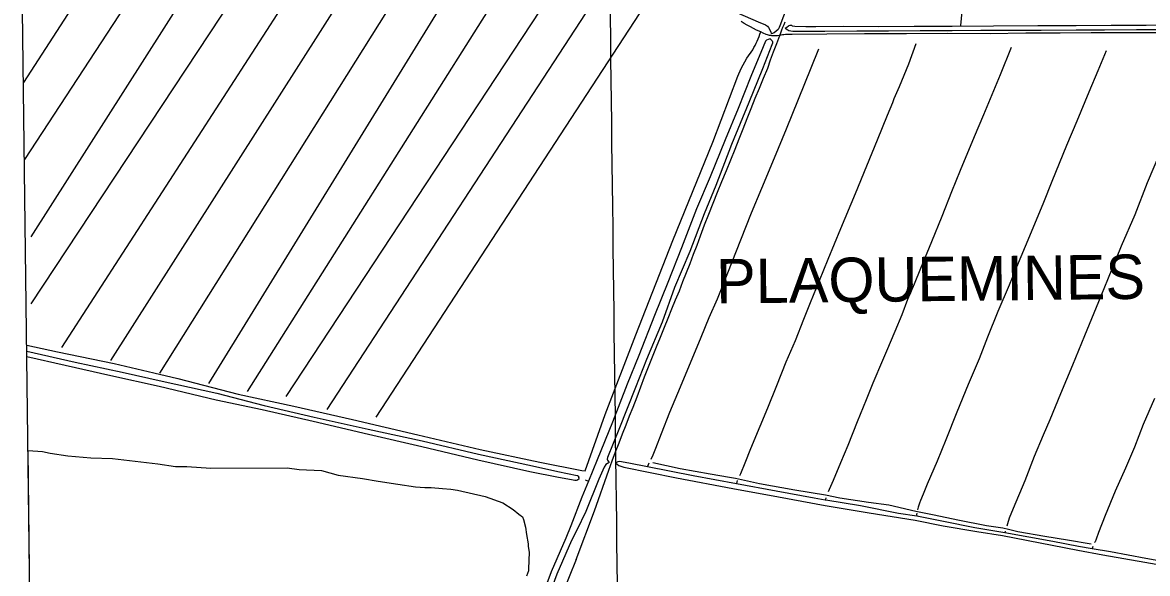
# Model space of a CAD drawing. Extents: x 3734862 to 3772949, y 391520 to 417239.
# Drawn here: x 3738996 to 3744064, y 399494 to 401975 of the extents above; entities that cross this region are included whole.
import ezdxf

# ---------------------------------------------------------------- set-up
doc = ezdxf.new("R2010")
doc.units = 0
for name, color, linetype in [('V-DTCH-CNTR', 7, 'Continuous'), ('V-GRID-FRAM', 7, 'Continuous'), ('V-GRID-MAJR', 7, 'Continuous'), ('V-SITE-VEGE', 7, 'Continuous'), ('V-TOPO-GNAM-IDEN', 7, 'Continuous'), ('V-TOPO-SHOR', 7, 'Continuous')]:
    doc.layers.add(name, color=color, linetype=linetype)

msp = doc.modelspace()

# ---------------------------------------------------------------- linework, layer by layer
at = {"layer": 'V-DTCH-CNTR'}
for points in [[(3741637.2, 399960.4), (3741652.4, 400001.1), (3741667.7, 400041.8), (3741683.2, 400082.4), (3741698.9, 400122.9), (3741714.8, 400163.4), (3741730.9, 400203.7), (3741747.2, 400244), (3741764.1, 400289.2), (3741781.2, 400334.4), (3741798.4, 400379.5), (3741815.8, 400424.5), (3741833.4, 400469.5), (3741851.2, 400514.4), (3741869.2, 400559.2), (3741887.3, 400603.9), (3741904.5, 400644.7), (3741921.4, 400685.5), (3741938.1, 400726.4), (3741954.7, 400767.4), (3741971, 400808.5), (3741987.2, 400849.6), (3742003.1, 400890.8), (3742018.9, 400932.1), (3742034.4, 400973.5), (3742049.8, 401015), (3742068.7, 401064), (3742087.8, 401113.1), (3742107.2, 401162), (3742126.7, 401210.8), (3742146.4, 401259.6), (3742166.4, 401308.3), (3742186.5, 401356.9), (3742206.8, 401405.5), (3742224.4, 401451.4), (3742242.1, 401497.2), (3742260.1, 401542.9), (3742278.2, 401588.6), (3742296.6, 401634.2), (3742315.1, 401679.7), (3742333.9, 401725.1), (3742352.9, 401770.4), (3742366, 401807.3), (3742379.5, 401844), (3742393.2, 401880.7), (3742407.1, 401917.3), (3742411.7, 401929.6), (3742416.5, 401941.8), (3742421.5, 401953.9), (3742426.6, 401966), (3742432, 401977.9)], [(3742346.2, 401921.2), (3742331.7, 401927.8), (3742321.1, 401932.8), (3742303, 401941.6), (3742288.9, 401948.8), (3742274.8, 401956.2), (3742260.8, 401963.8), (3742247, 401971.6), (3742233.2, 401979.5)], [(3742285.9, 401852.7), (3742291, 401862.4), (3742296, 401872.2), (3742300.7, 401882), (3742305.2, 401892), (3742309.5, 401902.1), (3742313.6, 401912.2), (3742317.5, 401922.5), (3742321.1, 401932.8)], [(3742411.5, 401918.1), (3742407.1, 401917.3), (3742404.3, 401916.7), (3742397.1, 401915.1), (3742391.9, 401914.8), (3742386.8, 401914.6), (3742381.6, 401914.7), (3742376.4, 401915), (3742371.3, 401915.5), (3742366.2, 401916.2), (3742361.1, 401917.1), (3742356.1, 401918.3), (3742351.1, 401919.6), (3742346.2, 401921.2)], [(3744183.5, 401928.6), (3743995.1, 401929.4), (3743810.5, 401929.2), (3743670, 401928), (3743515.6, 401926.8), (3743355.4, 401924.8), (3743161.8, 401925.4), (3742978.6, 401925.1), (3742789, 401923.7), (3742619.8, 401923.5), (3742462.7, 401921.3), (3742455.3, 401921.6), (3742448, 401921.6), (3742440.6, 401921.3), (3742433.3, 401920.9), (3742426, 401920.2), (3742418.7, 401919.2), (3742411.5, 401918.1)], [(3739014.9, 400522.6), (3739153.8, 400492.2), (3739408.1, 400440.3), (3739587.6, 400397.3), (3739695.6, 400372.2), (3739966.8, 400302.6), (3740217.9, 400248.3), (3740482.5, 400187.5), (3740776.1, 400119.5), (3741058, 400053.2), (3741325.9, 399996.2), (3741515.7, 399958.9), (3741530.6, 399956.2), (3741620.4, 400209.7), (3741758.2, 400568.6), (3741926, 400993.5), (3742105.4, 401436.2), (3742217.8, 401734.2), (3742232.6, 401768.4), (3742259.4, 401815.2), (3742285.9, 401852.7)], [(3741489.2, 399558.2), (3741572.7, 399776.7), (3741637.2, 399960.4)], [(3743810.2, 399627.1), (3743703.4, 399645), (3743601.2, 399661.6), (3743478.9, 399682.2), (3743438, 399692.6), (3743412.6, 399698.6), (3743338.6, 399708.9), (3743209.8, 399734.4), (3743103, 399756.7), (3743019.6, 399773.9), (3742898.9, 399802.2), (3742806.5, 399814), (3742677.7, 399834.2), (3742613.4, 399846.5), (3742474.8, 399870.3), (3742315.7, 399897.7), (3742208.1, 399922.9), (3742180.3, 399926.9), (3742092.8, 399941.5), (3741958.2, 399966.2), (3741834.7, 399992.6)], [(3741489.2, 399558.2), (3741364.2, 399245.8), (3741261.7, 398998.2), (3741153.5, 398730.5), (3741045.3, 398490.1)]]:
    msp.add_lwpolyline(points, dxfattribs=at)
at = {"layer": 'V-GRID-FRAM'}
msp.add_lwpolyline([(3738832.3, 415033.8), (3770599.2, 415447.4), (3770843.8, 397266.6), (3739061.1, 396852.8), (3738832.3, 415033.8)], dxfattribs=at)
at = {"layer": 'V-GRID-MAJR'}
msp.add_spline([(3741709.6, 396887.3), (3741633, 402946.6), (3741556.3, 409006.9), (3741479.6, 415067.2), (3741479.6, 415068.3)], degree=3, dxfattribs=at)
at = {"layer": 'V-SITE-VEGE'}
for p, q in [((3739031.5, 399202.2), (3739020.9, 400048.5)), ((3739020.9, 400048.5), (3739086.3, 400044.1)), ((3739086.3, 400044.1), (3739119.8, 400035.9)), ((3739119.8, 400035.9), (3739199.4, 400023.8)), ((3739199.4, 400023.8), (3739304.1, 400015.9)), ((3739304.1, 400015.9), (3739400.5, 400012.2)), ((3739400.5, 400012.2), (3739605.8, 399988.2)), ((3739605.8, 399988.2), (3739685.4, 399976)), ((3739685.4, 399976), (3739735.6, 399976.3)), ((3739735.6, 399976.3), (3739844.5, 399968.4)), ((3739844.5, 399968.4), (3740187.8, 399970.2)), ((3740187.8, 399970.2), (3740242.3, 399962.1)), ((3740242.3, 399962.1), (3740342.8, 399958.4)), ((3740342.8, 399958.4), (3740418.3, 399937.9)), ((3740418.3, 399937.9), (3740527.2, 399921.7)), ((3740527.2, 399921.7), (3740598.5, 399909.5)), ((3740598.5, 399909.5), (3740686.5, 399897.4)), ((3740686.5, 399897.4), (3740766.1, 399885.2)), ((3740766.1, 399885.2), (3740808, 399881.3)), ((3740808, 399881.3), (3740837.3, 399881.4)), ((3740837.3, 399881.4), (3740887.6, 399877.5)), ((3740887.6, 399877.5), (3740925.3, 399873.5)), ((3740925.3, 399873.5), (3740954.6, 399869.5)), ((3740954.6, 399869.5), (3741080.4, 399840.8)), ((3741080.4, 399840.8), (3741160.1, 399811.9)), ((3741160.1, 399811.9), (3741206.3, 399782.8)), ((3741206.3, 399782.8), (3741231.5, 399762)), ((3741231.5, 399762), (3741248.3, 399749.6)), ((3741248.3, 399749.6), (3741252.6, 399737)), ((3741252.6, 399737), (3741261.1, 399703.6)), ((3741261.1, 399703.6), (3741265.5, 399670.1)), ((3741265.5, 399670.1), (3741274, 399628.3)), ((3741274, 399628.3), (3741274.1, 399615.7)), ((3741274.1, 399615.7), (3741278.4, 399590.6)), ((3741278.4, 399590.6), (3741274.6, 399515.2)), ((3741274.7, 399506.8), (3741266.4, 399481.7)), ((3741274.6, 399515.2), (3741274.7, 399506.8))]:
    msp.add_line(p, q, dxfattribs=at)
at = {"layer": 'V-TOPO-SHOR'}
for p, q in [((3743222.3, 401962.5), (3743396.4, 403726.5)), ((3739787.1, 402925.7), (3739000, 401704.7)), ((3740007.6, 402890.9), (3739004.4, 401357.9)), ((3740193.3, 402832.9), (3739032.8, 401010.9)), ((3740390.6, 402763.3), (3739032.8, 400709.1)), ((3740529.9, 402612.4), (3739172.1, 400511.8)), ((3740738.8, 402566), (3739392.6, 400453.8)), ((3740924.4, 402484.7), (3739613.1, 400395.8)), ((3741098.5, 402403.5), (3739833.6, 400349.4)), ((3741284.2, 402333.9), (3740007.6, 400314.6)), ((3741481.5, 402264.2), (3740181.7, 400291.3)), ((3741632.4, 402171.4), (3740367.4, 400233.3)), ((3741829.7, 402101.8), (3740587.9, 400198.5)), ((3741817, 399991.5), (3741811.1, 399976.5)), ((3741530.6, 399915.5), (3741545.9, 399910.1)), ((3742215.9, 399912.6), (3742212.3, 399899.5)), ((3743817.4, 399615.5), (3743814.3, 399607.1))]:
    msp.add_line(p, q, dxfattribs=at)
for points in [[(3743107.9, 403761.9), (3743106.7, 403735.1), (3743100.7, 403710.7), (3743055.4, 403597.8), (3742962, 403363.6), (3742893.8, 403191.4), (3742807.6, 402977), (3742748, 402820.3), (3742695.2, 402681.5), (3742645.2, 402560.6), (3742579.9, 402391.6), (3742517.9, 402240.5), (3742452.6, 402080.1), (3742407, 401959.8), (3742404.6, 401952.9), (3742400.6, 401943.9), (3742381.9, 401928.7), (3742369.5, 401924.4)], [(3739446.6, 403230.2), (3739590.3, 403169.1), (3739774.9, 403091.3), (3740015.3, 402982.1), (3740220.1, 402894.6), (3740445.6, 402798.1), (3740659.6, 402701.9), (3740935.5, 402580.5), (3741156, 402482.4), (3741363.4, 402391.9), (3741564.9, 402301.5), (3741789.2, 402201.7), (3741935.8, 402141), (3742147.3, 402049.4), (3742309.6, 401978.1), (3742342.6, 401965.5), (3742352.1, 401958.6), (3742356.7, 401953.2), (3742365.8, 401936.8), (3742369.5, 401924.4)], [(3742431.4, 401950.4), (3742439.4, 401954.4), (3742446.3, 401960.2), (3742448.7, 401961.8), (3742453.2, 401962.7), (3742459.7, 401963.1), (3742463.3, 401961.1), (3742474.7, 401959.1), (3742525.2, 401957.7), (3742569.7, 401958), (3742692, 401958.6), (3742853.6, 401957.4), (3743011.9, 401958.6), (3743183.7, 401959.5), (3743369.8, 401960.9), (3743570.2, 401961.9), (3743742.4, 401962.4), (3743899.8, 401963.2), (3744057.3, 401964), (3744214.7, 401964.8)], [(3742431.4, 401950.4), (3742442.7, 401941.9), (3742448.4, 401939.4), (3742466.3, 401937.1), (3742610.7, 401936.6), (3742753.8, 401937.4), (3742897, 401938.1), (3743040.1, 401938.8), (3743183.3, 401939.6), (3743312.1, 401940.2), (3743455.3, 401941), (3743584.1, 401941.6), (3743741.6, 401942.4), (3743870.4, 401943.1), (3744013.5, 401943.8), (3744171, 401944.6)], [(3742363.5, 401901.1), (3742355, 401898.2), (3742347.7, 401895.3), (3742342.9, 401890.8), (3742332, 401866), (3742277.2, 401731.5), (3742219.6, 401588.1), (3742161.1, 401446.6), (3742093.4, 401280.1), (3742032.6, 401135.8), (3741964.5, 400960.5), (3741903.3, 400805.3), (3741843.3, 400655.7), (3741772, 400476.7), (3741720.4, 400347.6), (3741653.6, 400176), (3741584.3, 400006.6), (3741545.9, 399910.1), (3741515.9, 399838.7), (3741465.9, 399709.1), (3741443.5, 399653.9)], [(3742363.5, 401901.1), (3742372.5, 401892.6), (3742374.1, 401887.7), (3742374.5, 401882.8), (3742371.3, 401875.1), (3742329.2, 401767.3), (3742267.5, 401615.1), (3742190.1, 401426.7), (3742118.4, 401242.1), (3742066.8, 401113.3), (3742001.6, 400944.5), (3741933.1, 400781.5), (3741876.7, 400625.8), (3741807.1, 400457.8), (3741756.6, 400331.2), (3741682.2, 400143.3), (3741630.6, 400017.4), (3741629.8, 400009.7), (3741631.4, 400004), (3741633.9, 399999.6), (3741638.4, 399993.7)], [(3744327.8, 401884), (3744293.7, 401802.9), (3744219, 401627.6), (3744142.8, 401444.7), (3744062.8, 401253.7), (3744006.2, 401109.7), (3743945.2, 400968), (3743883.2, 400816.5), (3743843.1, 400718.4), (3743779.8, 400565.1), (3743725.5, 400432.9), (3743671.1, 400303.1), (3743623, 400185.8), (3743593.8, 400117.9), (3743553.7, 400021.8), (3743510.7, 399912.2), (3743458.1, 399786.7), (3743440.3, 399742.9), (3743432.3, 399718.7), (3743429.8, 399707.2)], [(3742581.7, 401854.7), (3742547.4, 401769.5), (3742489.7, 401628), (3742435.8, 401495.1), (3742381.6, 401364.9), (3742324.8, 401227.2), (3742278.2, 401116.2), (3742230.6, 400995.7), (3742171.1, 400846.9), (3742124.5, 400730.1), (3742087.1, 400645.5), (3742051, 400556.4), (3742004, 400442.1), (3741946.5, 400304.4), (3741910.6, 400218.7), (3741873.4, 400123.3), (3741847.1, 400057.5), (3741835.3, 400027), (3741826, 400008.2)], [(3743020.4, 401878.7), (3742986.4, 401787.2), (3742944.3, 401685.6), (3742920.2, 401631.2), (3742914.4, 401613.8), (3742891.4, 401556.6), (3742846.4, 401445.3), (3742797.4, 401328.9), (3742746.2, 401203.7), (3742681.3, 401047), (3742623.2, 400908.9), (3742584.9, 400812.3), (3742544.5, 400712.7), (3742513.8, 400638), (3742476.2, 400542.7), (3742434.9, 400446.6), (3742392.4, 400340.1), (3742351.8, 400239.5), (3742317.1, 400155.6), (3742274.7, 400055.9), (3742249.8, 399990.8), (3742230.2, 399943.6), (3742226.2, 399934.1)], [(3743450, 401862.4), (3743400.3, 401739.5), (3743325, 401560.2), (3743283.5, 401460.2), (3743219.1, 401309), (3743181, 401212.7), (3743136.7, 401101.9), (3743090.4, 400987.5), (3743040.4, 400867), (3743011.9, 400797.6), (3742982.7, 400728), (3742956.9, 400659.5), (3742924.8, 400584.7), (3742888.3, 400495.9), (3742870.2, 400453.1), (3742826.5, 400351.2), (3742796, 400276.3), (3742756.1, 400176.9), (3742713.1, 400070.8), (3742680.2, 399992.4), (3742647.4, 399913.7), (3742629.3, 399873.2), (3742624.7, 399862.4)], [(3743877.4, 401848.2), (3743839.5, 401757.1), (3743799.9, 401661.7), (3743745.5, 401531.7), (3743698.7, 401420.9), (3743632.7, 401259.1), (3743594.6, 401165.5), (3743524.5, 400994.6), (3743481.7, 400892.2), (3743440.9, 400792.9), (3743390.1, 400673.6), (3743343.5, 400558.3), (3743304.8, 400461.3), (3743256.2, 400346), (3743205.4, 400221), (3743155.5, 400096.2), (3743115.4, 400000.6), (3743071.2, 399897), (3743052.5, 399851.6), (3743041.2, 399823.8), (3743036.5, 399811.1), (3743033.4, 399801.4), (3743030.7, 399793), (3743027.4, 399780.8)], [(3739015.2, 400495.1), (3739233.2, 400445.9), (3739444.4, 400400.4), (3739624.8, 400360.1), (3739870.5, 400307.1), (3740083.7, 400250.7), (3740309.9, 400198.8), (3740552.8, 400144.6), (3740796.4, 400091.5), (3741049.8, 400031.3), (3741293.8, 399978.7), (3741407.7, 399953.8), (3741494.1, 399936.4), (3741496.5, 399936.4), (3741499.8, 399932.4), (3741501, 399927.1), (3741503, 399922.3)], [(3739015.5, 400471.2), (3739188.7, 400432.3), (3739393.1, 400385.6), (3739612, 400338.5), (3739867.8, 400276.7), (3740075.3, 400233.2), (3740305.6, 400180.9), (3740553.7, 400122.3), (3740795.3, 400066), (3741046.3, 400005.8), (3741281.4, 399953.9), (3741410.7, 399928.7), (3741468.2, 399917.2), (3741483.2, 399915.3), (3741490.9, 399914.9), (3741495.8, 399915.8), (3741503, 399922.3)], [(3744095.6, 400281.8), (3744044.5, 400166), (3744004.4, 400063.9), (3743964.1, 399968), (3743918.6, 399864.7), (3743873.6, 399755.5), (3743843.5, 399678.6), (3743832.6, 399648.3), (3743827.3, 399637.5), (3743825.5, 399634.2)], [(3741638.4, 399993.7), (3741634.1, 399991.4), (3741630.8, 399989), (3741624.1, 399984.6), (3741615.4, 399973.9), (3741592.1, 399918.6), (3741533.6, 399773.7), (3741493, 399690.3), (3741468.5, 399642.9)], [(3741667.7, 399992.7), (3741678.7, 399998.2), (3741684.7, 399999.8), (3741727.3, 399992.3), (3741811.1, 399976.5), (3742017.5, 399935.1), (3742212.3, 399899.5), (3742391.2, 399866.2), (3742561.4, 399835.1), (3742612.2, 399826.5), (3742614.9, 399826), (3742771.3, 399800.1), (3742942, 399766.2), (3743025.1, 399754.4), (3743144.2, 399729.9), (3743285.7, 399702.3), (3743420.9, 399678.5), (3743637.9, 399640.2)], [(3741667.7, 399992.7), (3741674.7, 399987), (3741682, 399981.2), (3741704.7, 399972.8), (3741941.4, 399924.6), (3742196, 399877.7), (3742401.4, 399840.3), (3742612.2, 399801.3), (3742810.4, 399767.1), (3743016.7, 399734.5), (3743143.1, 399709.3), (3743295.5, 399682.9), (3743409.8, 399666.1), (3743634.4, 399622.7)], [(3742615.3, 399835.5), (3742614, 399831.7), (3742612.2, 399826.5)], [(3743024.1, 399766.8), (3743023.4, 399760.5), (3743025.1, 399754.4)], [(3741443.5, 399653.9), (3741376.8, 399502.3), (3741302.9, 399301.1), (3741237.7, 399121.9), (3741165.8, 398945.5), (3741077, 398736.4), (3741000, 398542.2), (3740926.1, 398354.4), (3740872.8, 398226.8), (3740859.8, 398200.8), (3740851.1, 398192.5), (3740840.1, 398190.2)], [(3743423, 399685.5), (3743423, 399685.5), (3743420.9, 399678.5)], [(3741468.5, 399642.9), (3741402.1, 399492.1), (3741328.5, 399291.7), (3741263.2, 399112.1), (3741191, 398935), (3741102.2, 398726), (3741025.3, 398532.2), (3740951.4, 398344.1), (3740895.1, 398201.9), (3740895.1, 398184.9), (3740901, 398175.5)], [(3743634.4, 399622.7), (3743749.7, 399599.7), (3743862, 399578.7), (3744052.1, 399545.4), (3744204.2, 399518.4), (3744347.8, 399493.8), (3744520.7, 399464.2), (3744689.4, 399431.3), (3744847, 399403.1), (3744995.4, 399375), (3745218.1, 399330.2), (3745357.9, 399302.6), (3745455.9, 399286), (3745637.9, 399253.4), (3745838.6, 399214.9), (3745963.2, 399195.1), (3746065.1, 399178.1), (3746171, 399159.4), (3746202, 399153.9), (3746222.2, 399148.4), (3746232.1, 399142.5), (3746236.9, 399130.6), (3746244, 399132.1), (3746254, 399148.1)], [(3743637.9, 399640.2), (3743752.9, 399617.2), (3743814.3, 399607.1), (3743897.5, 399593.4), (3744055.4, 399562.9), (3744214.5, 399534.8)]]:
    msp.add_lwpolyline(points, dxfattribs=at)

# ---------------------------------------------------------------- texts
at = {"layer": 'V-TOPO-GNAM-IDEN'}
msp.add_text('PLAQUEMINES', height=200, rotation=0.6376, dxfattribs=at).set_placement((3742121.4, 400709.9))

doc.saveas('drawing.dxf')
